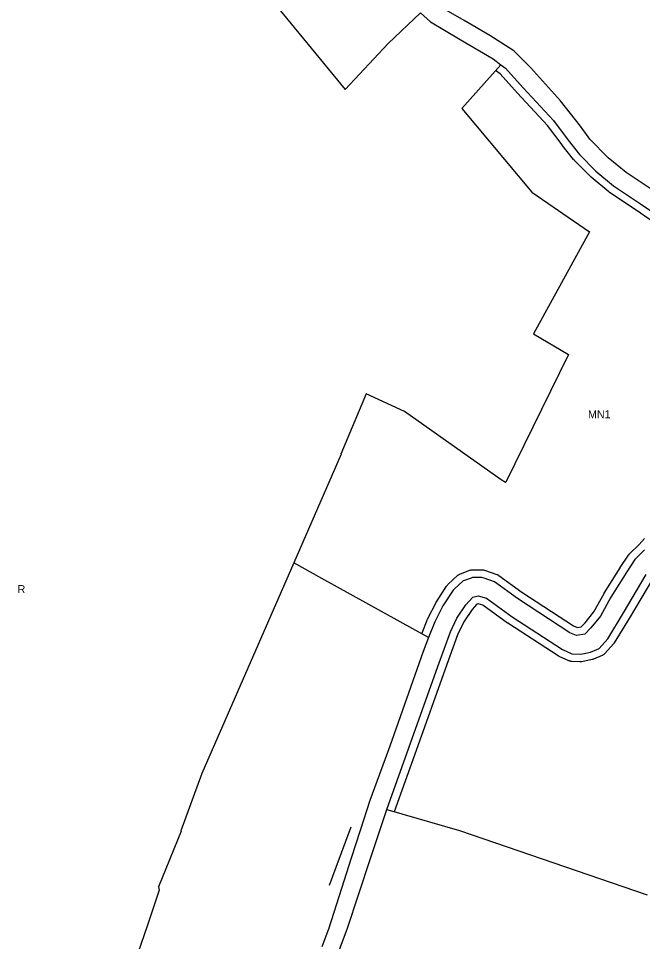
# Model space of a CAD drawing. Extents: x 7435758 to 7439981, y 5550649 to 5554049.
# Drawn here: x 7439172 to 7439577, y 5552845 to 5553445 of the extents above; entities that cross this region are included whole.
import ezdxf

# ---------------------------------------------------------------- set-up
doc = ezdxf.new("R2010")
doc.units = 0
for name, color, linetype in [('linie_rozgraniczające', 7, 'Continuous'), ('linie_zabudowy_nieprzekraczalne', 7, 'Continuous'), ('oznaczenia_przeznaczen', 7, 'Continuous')]:
    doc.layers.add(name, color=color, linetype=linetype)

msp = doc.modelspace()

# ---------------------------------------------------------------- linework, layer by layer
at = {"layer": 'linie_rozgraniczające'}
for p, q in [((7439301.05, 5553499.96), (7439384, 5553398.96)), ((7439411.84, 5553428.79), (7439432.82, 5553448.74)), ((7439432.82, 5553448.74), (7439439.32, 5553442.88)), ((7439461.17, 5553443.77), (7439449.57, 5553450.46)), ((7439439.32, 5553442.88), (7439458.54, 5553431.42)), ((7439477.97, 5553434.03), (7439461.17, 5553443.77)), ((7439384, 5553398.96), (7439411.84, 5553428.79)), ((7439458.54, 5553431.42), (7439480.15, 5553418.75)), ((7439493.49, 5553423.98), (7439477.97, 5553434.03)), ((7439504.34, 5553413.22), (7439493.49, 5553423.98)), ((7439480.15, 5553418.75), (7439485.04, 5553415.02)), ((7439485.04, 5553415.02), (7439459.63, 5553386.44)), ((7439485.04, 5553415.02), (7439488.08, 5553412.69)), ((7439488.08, 5553412.69), (7439499.54, 5553399.88)), ((7439523.71, 5553391.61), (7439504.34, 5553413.22)), ((7439499.54, 5553399.88), (7439519.15, 5553378.79)), ((7439536.75, 5553375.08), (7439523.71, 5553391.61)), ((7439459.63, 5553386.44), (7439505.06, 5553332.29)), ((7439519.15, 5553378.79), (7439528.79, 5553365.9)), ((7439542.82, 5553366.73), (7439536.75, 5553375.08)), ((7439528.79, 5553365.9), (7439536.2, 5553356.56)), ((7439554.78, 5553354.45), (7439542.82, 5553366.73)), ((7439536.2, 5553356.56), (7439546.8, 5553345.79)), ((7439566.36, 5553345.02), (7439554.78, 5553354.45)), ((7439546.8, 5553345.79), (7439558.26, 5553336.23)), ((7439584.03, 5553333.24), (7439566.36, 5553345.02)), ((7439558.26, 5553336.23), (7439575.65, 5553324.69)), ((7439505.06, 5553332.29), (7439542.61, 5553306.52)), ((7439575.65, 5553324.69), (7439598.96, 5553308.71)), ((7439542.61, 5553306.52), (7439506.32, 5553240.2)), ((7439506.32, 5553240.2), (7439529.01, 5553226.77)), ((7439529.01, 5553226.77), (7439488.29, 5553143.79)), ((7439397.71, 5553201.15), (7439381.25, 5553162.1)), ((7439422.48, 5553189.83), (7439397.71, 5553201.15)), ((7439485.25, 5553145.29), (7439422.48, 5553189.83)), ((7439381.35, 5553162.05), (7439350.6, 5553091.47)), ((7439381.25, 5553162.1), (7439381.35, 5553162.05)), ((7439488.18, 5553143.57), (7439485.25, 5553145.29)), ((7439488.29, 5553143.79), (7439488.18, 5553143.57)), ((7439578.39, 5553099.9), (7439572.13, 5553093.65)), ((7439572.13, 5553093.65), (7439566.73, 5553085.62)), ((7439350.6, 5553091.47), (7439290.94, 5552954.55)), ((7439368.93, 5553081.28), (7439350.6, 5553091.47)), ((7439438.12, 5553042.85), (7439368.93, 5553081.28)), ((7439465.69, 5553081.56), (7439461.38, 5553079.93)), ((7439466.73, 5553081.95), (7439465.69, 5553081.56)), ((7439469.44, 5553081.94), (7439466.73, 5553081.95)), ((7439472.72, 5553081.93), (7439469.44, 5553081.94)), ((7439474.12, 5553081.46), (7439472.72, 5553081.93)), ((7439480.91, 5553079.14), (7439474.12, 5553081.46)), ((7439566.73, 5553085.62), (7439556.46, 5553069.05)), ((7439564.69, 5553059), (7439579.46, 5553083.88)), ((7439460.57, 5553079.62), (7439454.83, 5553074.35)), ((7439461.38, 5553079.93), (7439460.57, 5553079.62)), ((7439495.94, 5553068.29), (7439480.91, 5553079.14)), ((7439454.05, 5553073.62), (7439447.43, 5553063.46)), ((7439454.83, 5553074.35), (7439454.05, 5553073.62)), ((7439462.4, 5553064.17), (7439466.87, 5553069.02)), ((7439466.87, 5553069.02), (7439470.4, 5553069.99)), ((7439470.4, 5553069.99), (7439475.67, 5553068.55)), ((7439556.46, 5553069.05), (7439549.67, 5553056.8)), ((7439447.43, 5553063.46), (7439442.12, 5553053.08)), ((7439456.58, 5553055.57), (7439462.4, 5553064.17)), ((7439475.67, 5553068.55), (7439492.35, 5553056.33)), ((7439529.92, 5553045.97), (7439495.94, 5553068.29)), ((7439554.4, 5553042.11), (7439564.69, 5553059)), ((7439442.12, 5553053.08), (7439438.12, 5553042.85)), ((7439452.27, 5553046.61), (7439456.58, 5553055.57)), ((7439492.35, 5553056.33), (7439525.04, 5553035.16)), ((7439549.67, 5553056.8), (7439543.46, 5553049.25)), ((7439444.13, 5553024.06), (7439452.27, 5553046.61)), ((7439534.15, 5553044.32), (7439529.92, 5553045.97)), ((7439539.59, 5553045.06), (7439534.15, 5553044.32)), ((7439543.46, 5553049.25), (7439539.59, 5553045.06)), ((7439438.12, 5553042.85), (7439434.57, 5553033.76)), ((7439548.89, 5553035.85), (7439554.4, 5553042.11)), ((7439434.57, 5553033.76), (7439412.96, 5552972.33)), ((7439525.04, 5553035.16), (7439531.19, 5553032.39)), ((7439540.15, 5553032.79), (7439543.22, 5553033.43)), ((7439543.22, 5553033.43), (7439548.89, 5553035.85)), ((7439531.19, 5553032.39), (7439536.69, 5553032.07)), ((7439536.69, 5553032.07), (7439540.15, 5553032.79)), ((7439425.28, 5552971.29), (7439444.13, 5553024.06)), ((7439412.96, 5552972.33), (7439399.94, 5552937.03)), ((7439410.99, 5552931.2), (7439425.28, 5552971.29)), ((7439290.94, 5552954.55), (7439277.23, 5552917.24)), ((7439399.94, 5552937.03), (7439393.66, 5552917.46)), ((7439400.35, 5552899.35), (7439410.95, 5552931.08)), ((7439410.95, 5552931.08), (7439410.99, 5552931.2)), ((7439410.95, 5552931.08), (7439458.23, 5552917.63)), ((7439277.61, 5552917.1), (7439262.73, 5552880.88)), ((7439277.23, 5552917.24), (7439277.61, 5552917.1)), ((7439393.66, 5552917.46), (7439387.92, 5552899.56)), ((7439458.23, 5552917.63), (7439579.94, 5552875.84)), ((7439387.92, 5552899.56), (7439381.61, 5552879.77)), ((7439385.2, 5552853.46), (7439400.35, 5552899.35)), ((7439263.21, 5552878.78), (7439255.67, 5552855.96)), ((7439262.73, 5552880.88), (7439263.21, 5552878.78)), ((7439381.61, 5552879.77), (7439373.25, 5552853.51)), ((7439255.67, 5552855.96), (7439238.89, 5552807.33)), ((7439373.25, 5552853.51), (7439368.77, 5552842.02)), ((7439372.45, 5552819.32), (7439385.2, 5552853.46))]:
    msp.add_line(p, q, dxfattribs=at)
at = {"layer": 'linie_zabudowy_nieprzekraczalne'}
for points in [[(7439596.13, 5553304.59), (7439572.86, 5553320.55), (7439555.49, 5553332.06), (7439555.37, 5553332.14), (7439555.11, 5553332.34), (7439555.05, 5553332.39), (7439543.59, 5553341.95), (7439543.41, 5553342.12), (7439543.23, 5553342.29), (7439532.64, 5553353.06), (7439532.58, 5553353.12), (7439532.36, 5553353.36), (7439532.29, 5553353.45), (7439524.88, 5553362.79), (7439524.79, 5553362.91), (7439515.31, 5553375.58), (7439495.88, 5553396.47), (7439495.82, 5553396.54), (7439484.67, 5553409.01), (7439481.64, 5553411.32)], [(7439433.74, 5553045.38), (7439437.46, 5553054.9), (7439437.55, 5553055.11), (7439437.67, 5553055.36), (7439442.97, 5553065.73), (7439443, 5553065.78), (7439443.16, 5553066.06), (7439443.24, 5553066.19), (7439449.86, 5553076.35), (7439449.96, 5553076.5), (7439450.16, 5553076.76), (7439450.37, 5553077.01), (7439450.6, 5553077.25), (7439450.66, 5553077.31), (7439457.19, 5553083.3), (7439457.37, 5553083.46), (7439457.63, 5553083.66), (7439457.9, 5553083.84), (7439458.18, 5553084.01), (7439458.48, 5553084.16), (7439458.78, 5553084.28), (7439458.8, 5553084.29), (7439464.96, 5553086.63), (7439465.24, 5553086.72), (7439465.56, 5553086.81), (7439465.88, 5553086.88), (7439466.2, 5553086.92), (7439466.53, 5553086.95), (7439466.75, 5553086.95), (7439472.74, 5553086.93), (7439472.85, 5553086.93), (7439473.17, 5553086.91), (7439473.5, 5553086.87), (7439473.82, 5553086.81), (7439474.14, 5553086.73), (7439474.34, 5553086.67), (7439482.52, 5553083.87), (7439482.63, 5553083.83), (7439482.94, 5553083.71), (7439483.23, 5553083.57), (7439483.52, 5553083.41), (7439483.79, 5553083.23), (7439483.84, 5553083.19), (7439498.77, 5553072.41), (7439532.23, 5553050.43), (7439534.76, 5553049.44), (7439537.14, 5553049.77), (7439539.69, 5553052.54), (7439545.52, 5553059.62), (7439552.09, 5553071.48), (7439552.2, 5553071.66), (7439552.21, 5553071.69), (7439562.48, 5553088.25), (7439562.58, 5553088.41), (7439567.99, 5553096.44), (7439568.05, 5553096.53), (7439568.24, 5553096.79), (7439568.46, 5553097.04), (7439568.6, 5553097.19), (7439574.79, 5553103.36), (7439578.36, 5553107.23)], [(7439583.47, 5553080.85), (7439568.99, 5553056.44), (7439568.96, 5553056.39), (7439568.95, 5553056.39), (7439558.67, 5553039.51), (7439558.66, 5553039.51), (7439558.48, 5553039.23), (7439558.29, 5553038.97), (7439558.15, 5553038.81), (7439552.64, 5553032.55), (7439552.56, 5553032.46), (7439552.33, 5553032.23), (7439552.09, 5553032.01), (7439551.83, 5553031.81), (7439551.56, 5553031.63), (7439551.28, 5553031.46), (7439550.99, 5553031.32), (7439550.86, 5553031.26), (7439545.19, 5553028.83), (7439545.02, 5553028.76), (7439544.71, 5553028.66), (7439544.4, 5553028.57), (7439544.25, 5553028.53), (7439537.72, 5553027.17), (7439537.55, 5553027.14), (7439537.22, 5553027.09), (7439536.9, 5553027.07), (7439536.57, 5553027.07), (7439536.4, 5553027.07), (7439530.9, 5553027.4), (7439530.74, 5553027.41), (7439530.42, 5553027.45), (7439530.1, 5553027.51), (7439529.78, 5553027.6), (7439529.47, 5553027.7), (7439529.17, 5553027.82), (7439529.14, 5553027.83), (7439522.99, 5553030.6), (7439522.72, 5553030.73), (7439522.44, 5553030.89), (7439522.33, 5553030.96), (7439489.64, 5553052.14), (7439489.47, 5553052.25), (7439489.4, 5553052.3), (7439473.46, 5553063.97), (7439470.4, 5553064.81), (7439469.57, 5553064.58), (7439466.33, 5553061.06), (7439460.92, 5553053.07), (7439456.89, 5553044.68), (7439448.84, 5553022.37), (7439429.99, 5552969.61), (7439415.77, 5552929.71)], [(7439373.83, 5552882.06), (7439378.12, 5552893.7), (7439387.79, 5552919.92)]]:
    msp.add_lwpolyline(points, dxfattribs=at)

# ---------------------------------------------------------------- texts
at = {"layer": 'oznaczenia_przeznaczen'}
for s, p in [('MN1', (7439541.61, 5553185.34)), ('R', (7439171.36, 5553071.75))]:
    msp.add_text(s, height=5.2, dxfattribs=at).set_placement(p)

doc.saveas('drawing.dxf')
